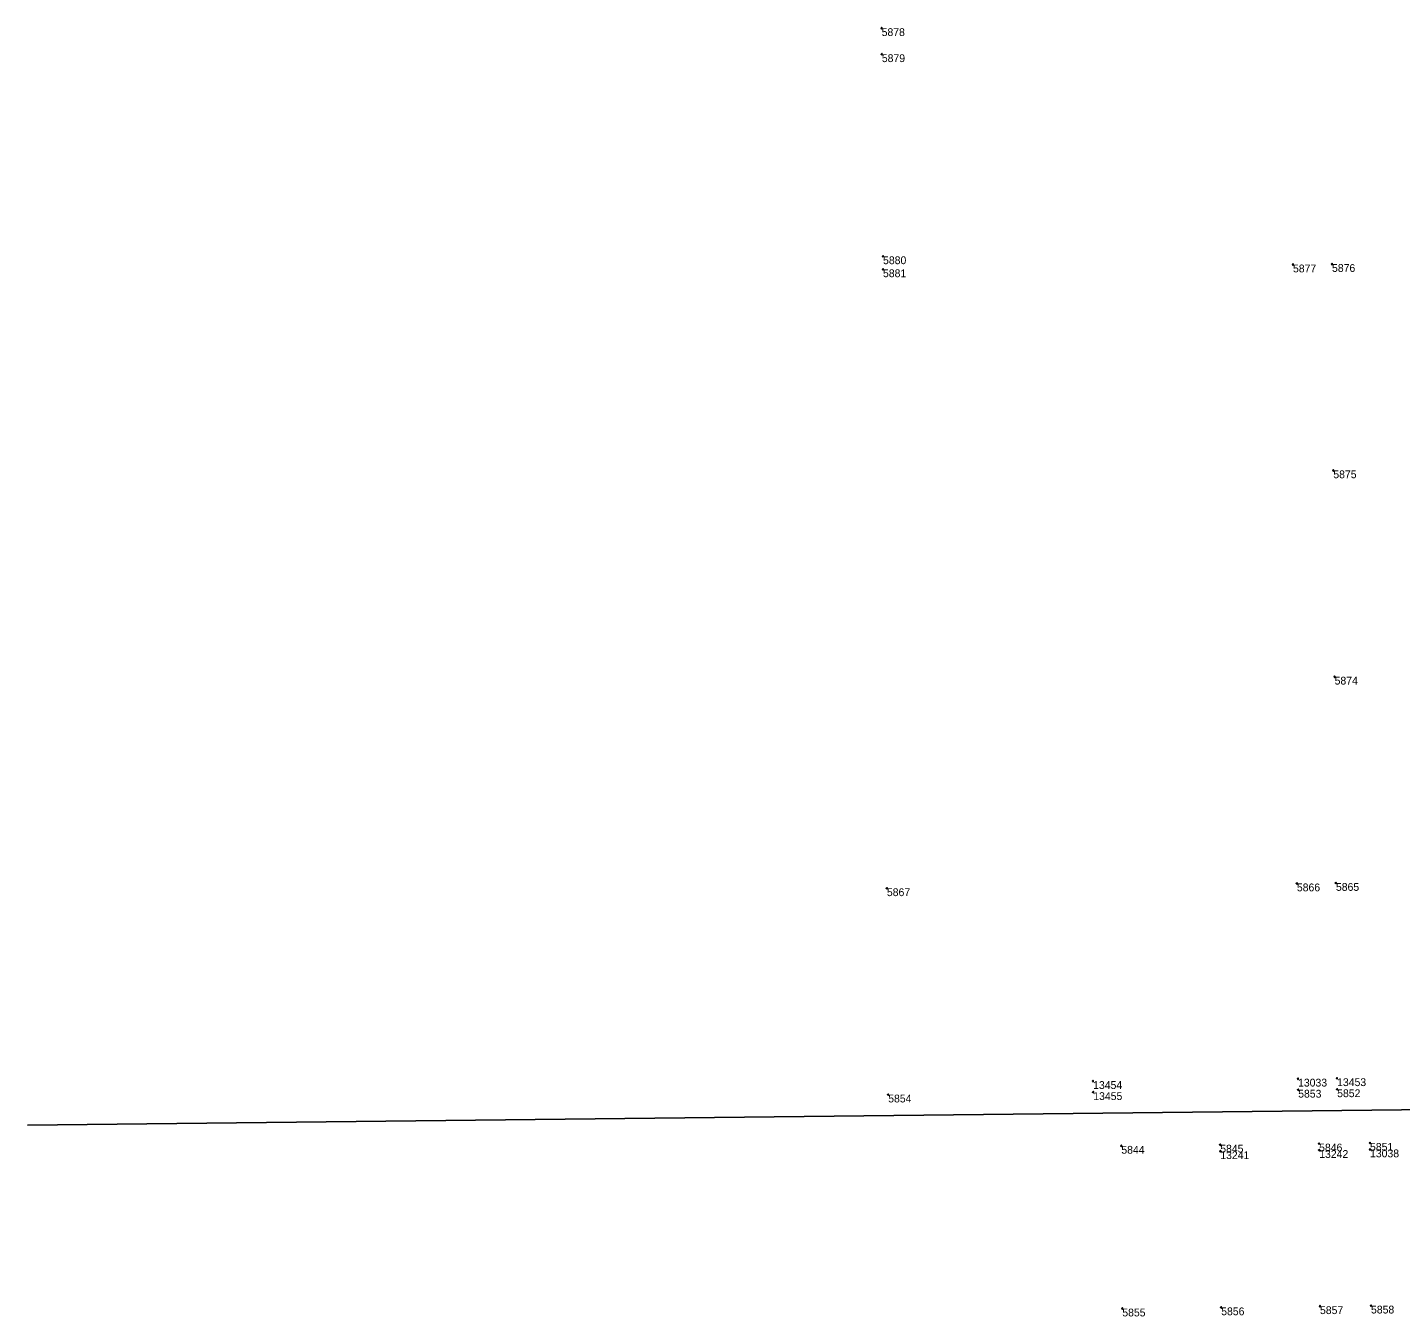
# Model space of a CAD drawing. Extents: x 2145146 to 2158053, y 137507 to 150829.
# Drawn here: x 2148244 to 2150354, y 147961 to 149942 of the extents above; entities that cross this region are included whole.
import ezdxf

# ---------------------------------------------------------------- set-up
doc = ezdxf.new("R2010")
doc.units = 0
doc.layers.add('ALIGN_Cogo Points', color=7, linetype='Continuous')
doc.layers.add('PLSS_Section Line', color=7, linetype='Continuous')

msp = doc.modelspace()

# ---------------------------------------------------------------- linework, layer by layer
at = {"layer": 'ALIGN_Cogo Points'}
for points in [[(2149556.7, 149940.7), (2149556.7, 149941.9), (2149556.7, 149940.7), (2149555.5, 149940.7), (2149556.7, 149940.7), (2149556.7, 149939.5), (2149556.7, 149940.7), (2149557.9, 149940.7)], [(2149557, 149900.7), (2149557, 149901.9), (2149557, 149900.7), (2149555.8, 149900.7), (2149557, 149900.7), (2149557, 149899.5), (2149557, 149900.7), (2149558.2, 149900.7)], [(2149558.9, 149590.2), (2149558.9, 149591.4), (2149558.9, 149590.2), (2149557.7, 149590.2), (2149558.9, 149590.2), (2149558.9, 149589), (2149558.9, 149590.2), (2149560.1, 149590.2)], [(2150188.8, 149577.6), (2150188.8, 149578.8), (2150188.8, 149577.6), (2150187.6, 149577.6), (2150188.8, 149577.6), (2150188.8, 149576.4), (2150188.8, 149577.6), (2150190, 149577.6)], [(2150248.8, 149578.3), (2150248.8, 149579.5), (2150248.8, 149578.3), (2150247.6, 149578.3), (2150248.8, 149578.3), (2150248.8, 149577.1), (2150248.8, 149578.3), (2150250, 149578.3)], [(2149558.8, 149570.2), (2149558.8, 149571.4), (2149558.8, 149570.2), (2149557.6, 149570.2), (2149558.8, 149570.2), (2149558.8, 149569), (2149558.8, 149570.2), (2149560, 149570.2)], [(2150250.8, 149261.3), (2150250.8, 149262.5), (2150250.8, 149261.3), (2150249.6, 149261.3), (2150250.8, 149261.3), (2150250.8, 149260.1), (2150250.8, 149261.3), (2150252, 149261.3)], [(2150252.8, 148944.3), (2150252.8, 148945.5), (2150252.8, 148944.3), (2150251.6, 148944.3), (2150252.8, 148944.3), (2150252.8, 148943.1), (2150252.8, 148944.3), (2150254, 148944.3)], [(2150194.8, 148626.6), (2150194.8, 148627.8), (2150194.8, 148626.6), (2150193.6, 148626.6), (2150194.8, 148626.6), (2150194.8, 148625.4), (2150194.8, 148626.6), (2150196, 148626.6)], [(2150254.8, 148627.3), (2150254.8, 148628.5), (2150254.8, 148627.3), (2150253.6, 148627.3), (2150254.8, 148627.3), (2150254.8, 148626.1), (2150254.8, 148627.3), (2150256, 148627.3)], [(2149564.8, 148619.2), (2149564.8, 148620.4), (2149564.8, 148619.2), (2149563.6, 148619.2), (2149564.8, 148619.2), (2149564.8, 148618), (2149564.8, 148619.2), (2149566, 148619.2)], [(2149881.7, 148322.9), (2149881.7, 148324.1), (2149881.7, 148322.9), (2149880.5, 148322.9), (2149881.7, 148322.9), (2149881.7, 148321.7), (2149881.7, 148322.9), (2149882.9, 148322.9)], [(2150196.6, 148326.6), (2150196.6, 148327.8), (2150196.6, 148326.6), (2150195.4, 148326.6), (2150196.6, 148326.6), (2150196.6, 148325.4), (2150196.6, 148326.6), (2150197.8, 148326.6)], [(2150196.8, 148309.6), (2150196.8, 148310.8), (2150196.8, 148309.6), (2150195.6, 148309.6), (2150196.8, 148309.6), (2150196.8, 148308.4), (2150196.8, 148309.6), (2150198, 148309.6)], [(2150256.6, 148327.3), (2150256.6, 148328.5), (2150256.6, 148327.3), (2150255.4, 148327.3), (2150256.6, 148327.3), (2150256.6, 148326.1), (2150256.6, 148327.3), (2150257.8, 148327.3)], [(2150256.7, 148310.3), (2150256.7, 148311.5), (2150256.7, 148310.3), (2150255.5, 148310.3), (2150256.7, 148310.3), (2150256.7, 148309.1), (2150256.7, 148310.3), (2150257.9, 148310.3)], [(2149566.8, 148302.2), (2149566.8, 148303.4), (2149566.8, 148302.2), (2149565.6, 148302.2), (2149566.8, 148302.2), (2149566.8, 148301), (2149566.8, 148302.2), (2149568, 148302.2)], [(2149881.9, 148305.9), (2149881.9, 148307.1), (2149881.9, 148305.9), (2149880.7, 148305.9), (2149881.9, 148305.9), (2149881.9, 148304.7), (2149881.9, 148305.9), (2149883.1, 148305.9)], [(2150077, 148225.2), (2150077, 148226.4), (2150077, 148225.2), (2150075.8, 148225.2), (2150077, 148225.2), (2150077, 148224), (2150077, 148225.2), (2150078.2, 148225.2)], [(2150229, 148226.9), (2150229, 148228.1), (2150229, 148226.9), (2150227.8, 148226.9), (2150229, 148226.9), (2150229, 148225.7), (2150229, 148226.9), (2150230.2, 148226.9)], [(2150307.2, 148227.9), (2150307.2, 148229.1), (2150307.2, 148227.9), (2150306, 148227.9), (2150307.2, 148227.9), (2150307.2, 148226.7), (2150307.2, 148227.9), (2150308.4, 148227.9)], [(2149925, 148223.4), (2149925, 148224.6), (2149925, 148223.4), (2149923.8, 148223.4), (2149925, 148223.4), (2149925, 148222.2), (2149925, 148223.4), (2149926.2, 148223.4)], [(2150077.1, 148215.2), (2150077.1, 148216.4), (2150077.1, 148215.2), (2150075.9, 148215.2), (2150077.1, 148215.2), (2150077.1, 148214), (2150077.1, 148215.2), (2150078.3, 148215.2)], [(2150229.1, 148216.9), (2150229.1, 148218.1), (2150229.1, 148216.9), (2150227.9, 148216.9), (2150229.1, 148216.9), (2150229.1, 148215.7), (2150229.1, 148216.9), (2150230.3, 148216.9)], [(2150307.2, 148217.9), (2150307.2, 148219.1), (2150307.2, 148217.9), (2150306, 148217.9), (2150307.2, 148217.9), (2150307.2, 148216.7), (2150307.2, 148217.9), (2150308.4, 148217.9)], [(2149926.5, 147973.4), (2149926.5, 147974.6), (2149926.5, 147973.4), (2149925.3, 147973.4), (2149926.5, 147973.4), (2149926.5, 147972.2), (2149926.5, 147973.4), (2149927.7, 147973.4)], [(2150078.5, 147975.2), (2150078.5, 147976.4), (2150078.5, 147975.2), (2150077.3, 147975.2), (2150078.5, 147975.2), (2150078.5, 147974), (2150078.5, 147975.2), (2150079.7, 147975.2)], [(2150230.3, 147977), (2150230.3, 147978.2), (2150230.3, 147977), (2150229.1, 147977), (2150230.3, 147977), (2150230.3, 147975.8), (2150230.3, 147977), (2150231.5, 147977)], [(2150308.7, 147977.9), (2150308.7, 147979.1), (2150308.7, 147977.9), (2150307.5, 147977.9), (2150308.7, 147977.9), (2150308.7, 147976.7), (2150308.7, 147977.9), (2150309.9, 147977.9)]]:
    msp.add_lwpolyline(points, dxfattribs=at)
at = {"layer": 'PLSS_Section Line'}
msp.add_line((2150890, 148284.8), (2148244.1, 148255.4), dxfattribs=at)

# ---------------------------------------------------------------- texts
at = {"layer": 'ALIGN_Cogo Points'}
for s, p in [('5878', (2149556.7, 149928.7)), ('5879', (2149557, 149888.7)), ('5880', (2149558.9, 149578.2)), ('5877', (2150188.8, 149565.6)), ('5876', (2150248.8, 149566.3)), ('5881', (2149558.8, 149558.2)), ('5875', (2150250.8, 149249.3)), ('5874', (2150252.8, 148932.3)), ('5865', (2150254.8, 148615.3)), ('5867', (2149564.8, 148607.2)), ('5866', (2150194.8, 148614.6)), ('13454', (2149881.7, 148310.9)), ('13033', (2150196.6, 148314.6)), ('5852', (2150256.7, 148298.3)), ('13453', (2150256.6, 148315.3)), ('5854', (2149566.8, 148290.2)), ('13455', (2149881.9, 148293.9)), ('5853', (2150196.8, 148297.6)), ('5846', (2150229, 148214.9)), ('5851', (2150307.2, 148215.9)), ('5844', (2149925, 148211.4)), ('5845', (2150077, 148213.2)), ('13241', (2150077.1, 148203.2)), ('13242', (2150229.1, 148204.9)), ('13038', (2150307.2, 148205.9)), ('5855', (2149926.5, 147961.4)), ('5856', (2150078.5, 147963.2)), ('5857', (2150230.3, 147965)), ('5858', (2150308.7, 147965.9))]:
    msp.add_text(s, height=12, dxfattribs=at).set_placement(p)

doc.saveas('drawing.dxf')
